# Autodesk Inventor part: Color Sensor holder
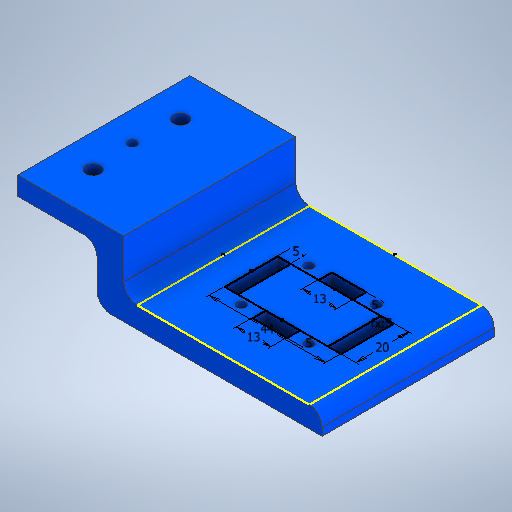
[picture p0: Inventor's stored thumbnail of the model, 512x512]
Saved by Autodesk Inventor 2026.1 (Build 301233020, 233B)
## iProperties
Created: 2026-11
Part Number: Color Sensor holder
Material: Generic
Document SubType Name: Modeling
Designer: hp
Density: 1 g/cm^3
Appearance: Default
Author: hp
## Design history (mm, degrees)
sketch "Sketch1"
  geometry: L1 (0, 0)-(0, 28); L2 (0, 28)-(10, 28); L3 (10, 28)-(10, 8); L4 (10, 8)-(85, 8); L5 (85, 8)-(85, 0); L6 (85, 0)-(0, 0); L7 (47.5, 8)-(47.5, 0); L8 (10, 0)-(95, 0); L9 (0, 21)-(-30, 21); L10 (-30, 21)-(-30, 28); L11 (-30, 28)-(0, 28); 1 further point
  constraints: 22 end point, 8 perpendicular, 2 point on line, 2 symmetric about line, 1 horizontal, 1 midpoint, 1 vertical
  dimensions: "d0" = 28 distance of L1.start L1.end; "d1" = 10 distance of L1.end L2.end; "d2" = 20 distance of L2.end L3.end; "d3" = 75 distance of L3.end L4.end; "d18" = 30 distance of L9.start L9.end; "d19" = 7 distance of L9.end L10.end
extrude "Extrusion1" new body sketch "Sketch1" distance "d4" = 65; taper "d5" = 0 deg
fillet "Fillet1" dims "d6" = 5
fillet "Fillet2" dims "d7" = 5
sketch "Sketch2"
  geometry: L1 (65, 65)-(65, 0) reference; L2 (65, 65)-(0, 65) reference; L3 (0, 0)-(0, 65) reference; L4 (65, 0)-(0, 0) reference; L5 (10.5, 42.5)-(54.5, 42.5); L6 (54.5, 42.5)-(54.5, 22.5); L7 (54.5, 22.5)-(10.5, 22.5); L8 (10.5, 22.5)-(10.5, 42.5); L9 (26, 22.5)-(39, 22.5); L10 (39, 22.5)-(39, 17.5); L11 (39, 17.5)-(26, 17.5); L12 (26, 17.5)-(26, 22.5); L13 (26, 47.5)-(39, 47.5); L14 (39, 47.5)-(39, 42.5); L15 (26, 42.5)-(26, 47.5); L16 (39, 42.5)-(26, 42.5); L17 (15.5, 22.5)-(15.5, 42.5); L18 (49.5, 22.5)-(49.5, 42.5); 10 further points
  constraints: 28 end point, 7 midpoint, 6 parallel, 5 perpendicular, 4 point on line, 3 horizontal, 1 horizontal alignment, 1 vertical alignment
  dimensions: "d8" = 44 distance of L6.end L7.end; "d9" = 20 distance of L5.end L6.end; "d10" = 13 distance of L10.end L11.end; "d11" = 5 distance of L9.end L10.end; "d12" = 13 distance of L14.end L15.start; "d13" = 5 distance of L13.end L14.end; "d16" = 5 distance between parallel lines of L17 L8; "d17" = 5 distance between parallel lines of L6 L18 (= d16)
extrude "Extrusion2" cut sketch "Sketch2" extent not by distance; stored distance "d14" = 60; taper "d15" = 0 deg
fillet "Fillet3" dims "d20" = 5
sketch "Sketch3"
  geometry: 1 further point
hole "Hole1" sketch "Sketch3" at (11.3, 32.987) diameter "d21" = 3.4; stored, may be unused: countersink angle "d25" = 90 deg, drill point angle "d27" = 0 deg; dims "d22" = 6, "d23" = 4, "d24" = 2, "d26" = 8
sketch "Sketch4"
  geometry: L1 (25, 65)-(25, 0) reference; L2 (0, 65)-(25, 65) reference; L3 (0, 0)-(0, 65) reference; L4 (0, 0)-(25, 0) reference; C1 r 1.7 at (11.3, 32.987) reference; C2 r 2.5 at (12.5, 49); C3 r 2.5 at (12.5, 16); 5 further points
  constraints: 2 centre point, 2 coincident, 2 midpoint, 2 vertical alignment
  dimensions: "d28" = 5 diameter of C2; "d29" = 5 diameter of C3 (= d28); "d30" = 16 distance from line of L2 C2.centre; "d31" = 16 distance from line of L4 C3.centre (= d30)
  node "Projected Loop2"
sketch "Sketch5"
  geometry: 2 further points
hole "Hole2" sketch "Sketch5" at (12.5, 49), (12.5, 16) diameter "d32" = 5.5; stored, may be unused: countersink angle "d36" = 90 deg, drill point angle "d38" = 0 deg; dims "d33" = 6, "d34" = 4, "d35" = 2, "d37" = 8
sketch "Sketch6"
  geometry: 4 further points
hole "Hole3" sketch "Sketch6" at (-50.25, 45.25), (-24.75, 45.25), (-24.75, 19.75), (-50.25, 19.75) diameter "d39" = 3.4; stored, may be unused: countersink angle "d43" = 90 deg, drill point angle "d45" = 0 deg; dims "d40" = 6, "d41" = 4, "d42" = 2, "d44" = 8
body "Solid1"
node "Projected Loop1"
